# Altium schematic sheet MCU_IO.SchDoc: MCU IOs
size A3; Date: Not used; ApprovedBy: Not used; CheckedBy: Not used; Author: Not used; CompanyName: STMicroelectronics; DrawnBy: Not used; Engineer: Not used; Organization: Not used; Address1: Not used; Address2: Not used; Address3: Not used; Address4: Not used; DocumentNumber: Not used; Revision: Not used; SheetNumber: 3; SheetTotal: 16
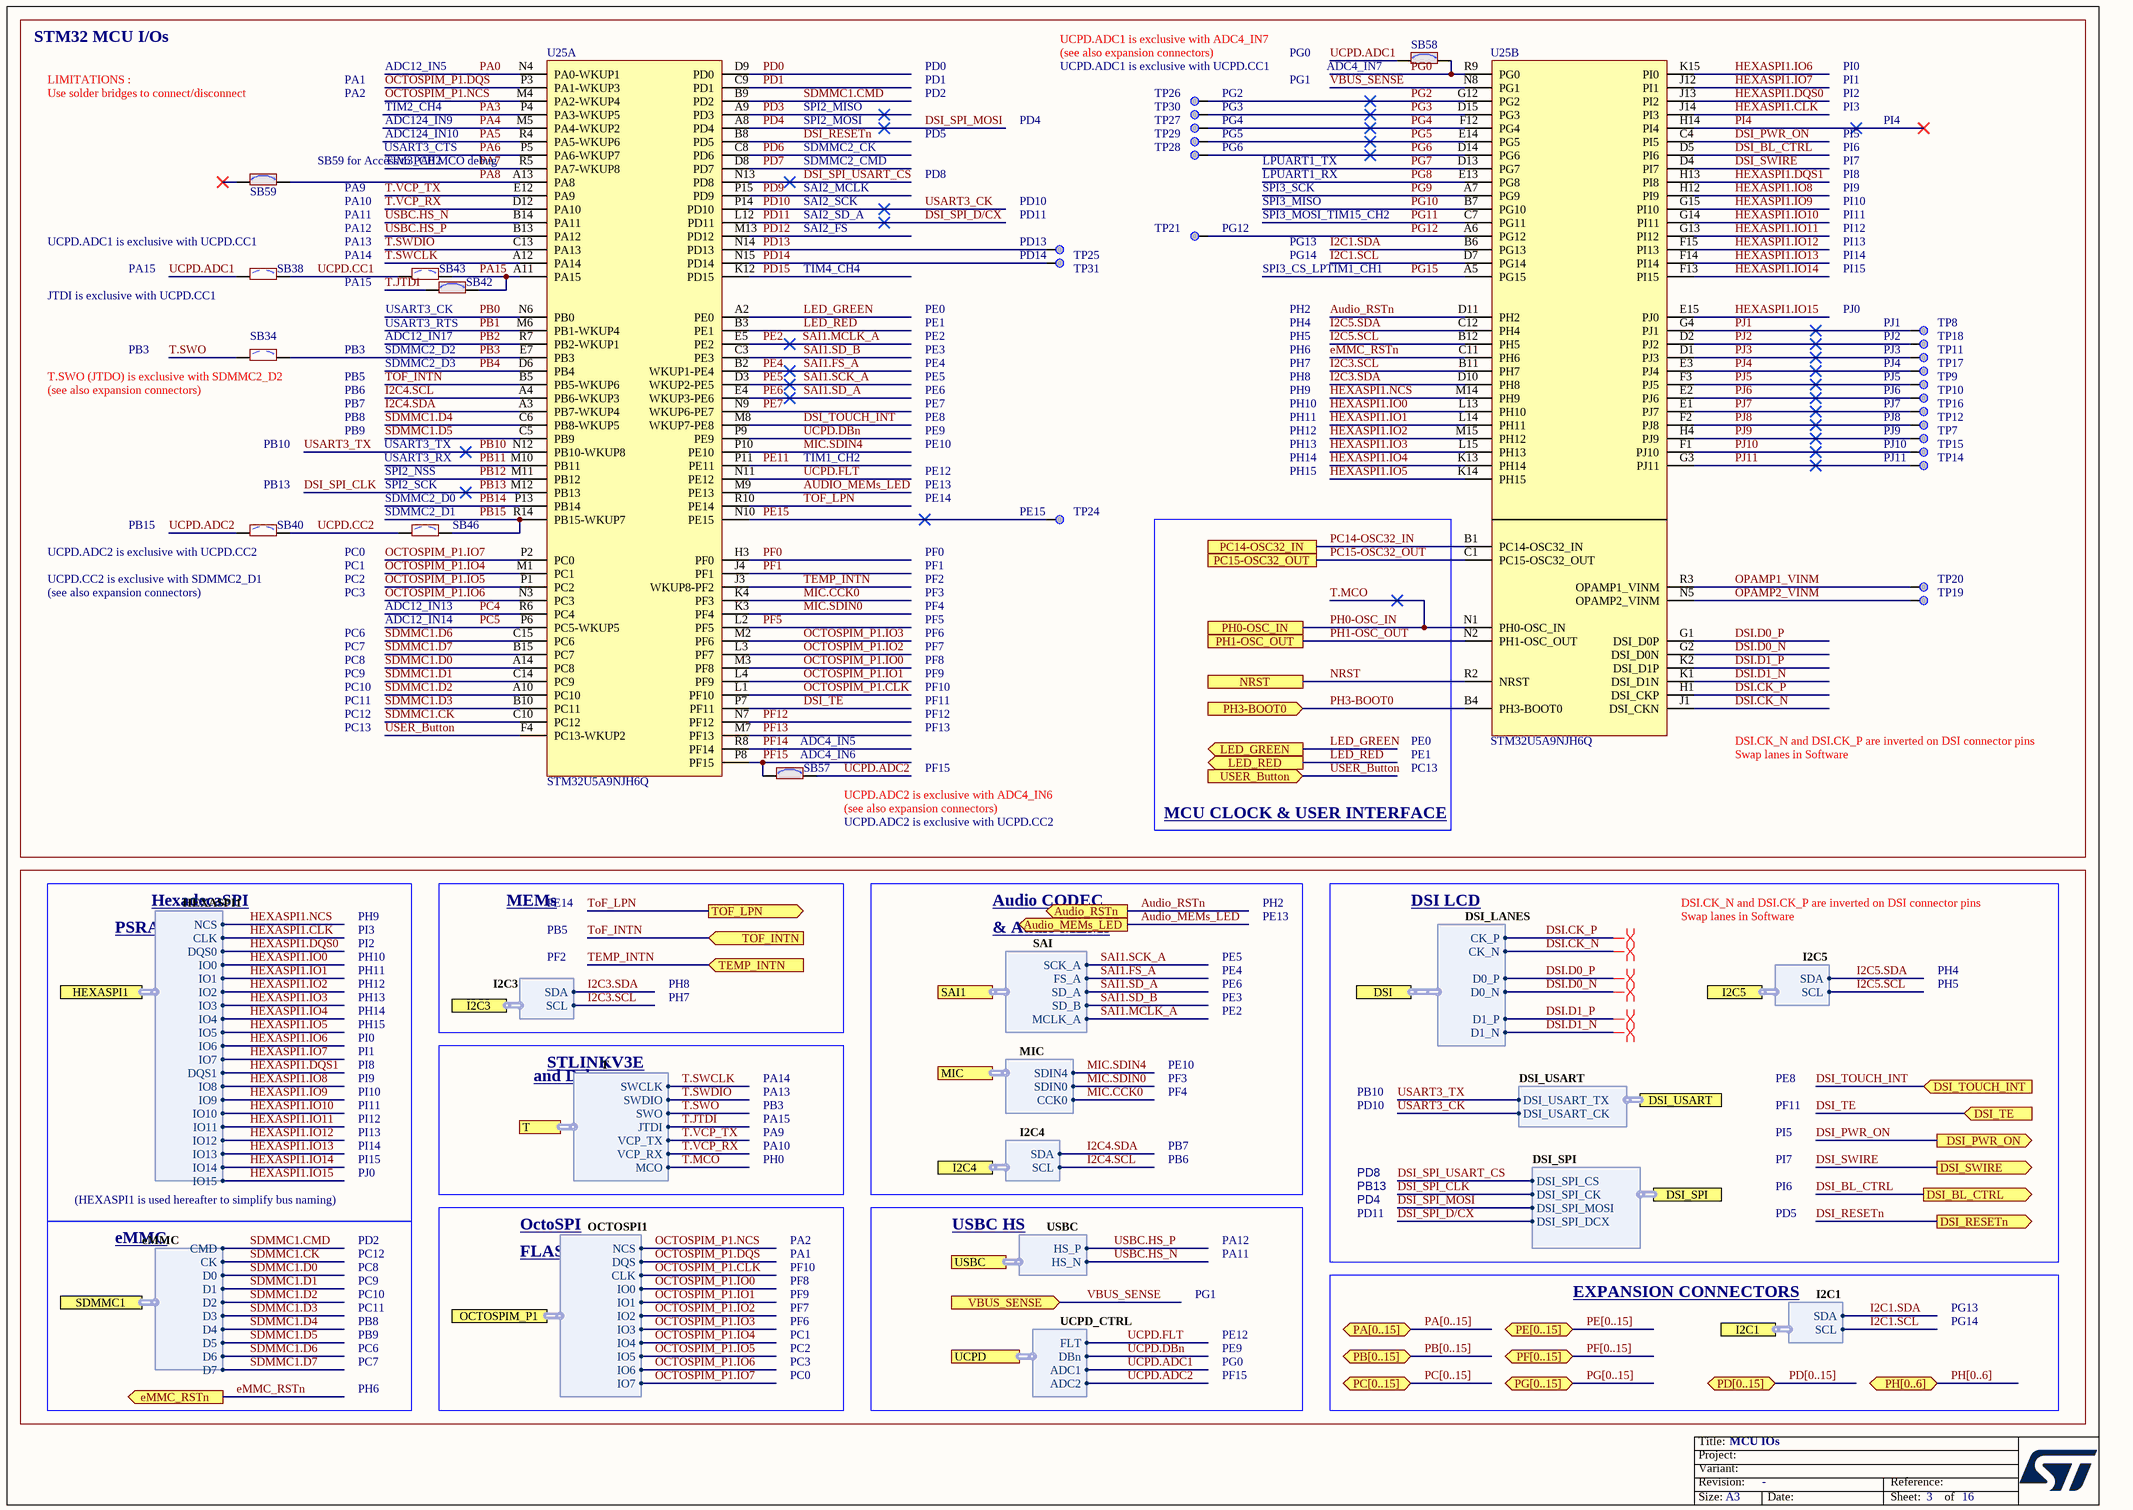
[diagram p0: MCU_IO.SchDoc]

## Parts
SB34  SB_OFF  [SOLDER-BRIDGE_R0402-0R]  (value not drawn)
SB38  SB_OFF  [SOLDER-BRIDGE_R0402-0R]  (value not drawn)
SB40  SB_OFF  [SOLDER-BRIDGE_R0402-0R]  (value not drawn)
SB42  SB_ON  [SOLDER-BRIDGE_R0402-0R]  (value not drawn)
SB43  SB_OFF  [SOLDER-BRIDGE_R0402-0R]  (value not drawn)
SB46  SB_OFF  [SOLDER-BRIDGE_R0402-0R]  (value not drawn)
SB57  SB_ON  [SOLDER-BRIDGE_R0402-0R]  (value not drawn)
SB58  SB_ON  [SOLDER-BRIDGE_R0402-0R]  (value not drawn)
SB59  SB_ON  [SOLDER-BRIDGE_R0402-0R]  (value not drawn)
TP7  Test Point  [TP_SMD_1MM]  (value not drawn)  (no BOM)
TP8  Test Point  [TP_SMD_1MM]  (value not drawn)  (no BOM)
TP9  Test Point  [TP_SMD_1MM]  (value not drawn)  (no BOM)
TP10  Test Point  [TP_SMD_1MM]  (value not drawn)  (no BOM)
TP11  Test Point  [TP_SMD_1MM]  (value not drawn)  (no BOM)
TP12  Test Point  [TP_SMD_1MM]  (value not drawn)  (no BOM)
TP14  Test Point  [TP_SMD_1MM]  (value not drawn)  (no BOM)
TP15  Test Point  [TP_SMD_1MM]  (value not drawn)  (no BOM)
TP16  Test Point  [TP_SMD_1MM]  (value not drawn)  (no BOM)
TP17  Test Point  [TP_SMD_1MM]  (value not drawn)  (no BOM)
TP18  Test Point  [TP_SMD_1MM]  (value not drawn)  (no BOM)
TP19  Test Point  [TP_SMD_1MM]  (value not drawn)  (no BOM)
TP20  Test Point  [TP_SMD_1MM]  (value not drawn)  (no BOM)
TP21  Test Point  [TP_SMD_1MM]  (value not drawn)  (no BOM)
TP24  Test Point  [TP_SMD_1MM]  (value not drawn)  (no BOM)
TP25  Test Point  [TP_SMD_1MM]  (value not drawn)  (no BOM)
TP26  Test Point  [TP_SMD_1MM]  (value not drawn)  (no BOM)
TP27  Test Point  [TP_SMD_1MM]  (value not drawn)  (no BOM)
TP28  Test Point  [TP_SMD_1MM]  (value not drawn)  (no BOM)
TP29  Test Point  [TP_SMD_1MM]  (value not drawn)  (no BOM)
TP30  Test Point  [TP_SMD_1MM]  (value not drawn)  (no BOM)
TP31  Test Point  [TP_SMD_1MM]  (value not drawn)  (no BOM)
U25  value STM32U5A9NJH6Q  [ICC_TFBGA216_13X13_P080_H1P10_CODE-A0L2]  (hidden comment: STM32U599NJH6Q_BGA216_SMPS)  (parts A,B of 3)

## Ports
Audio_MEMs_LED (out), Audio_RSTn (out), DSI (harness DSI_LANES), DSI_BL_CTRL (out), DSI_PWR_ON (out), DSI_RESETn (out), DSI_SPI (harness DSI_SPI), DSI_SWIRE (out), DSI_TE (in), DSI_TOUCH_INT (in), DSI_USART (harness DSI_USART), eMMC_RSTn (out), HEXASPI1 (harness HEXASPI1), I2C1 (harness I2C1), I2C3 (harness I2C3), I2C4 (harness I2C4), I2C5 (harness I2C5), LED_GREEN (out), LED_RED (out), MIC (harness MIC), NRST, OCTOSPIM_P1 (harness OCTOSPI1), PA[0..15] (bidir), PB[0..15] (bidir), PC14-OSC32_IN, PC15-OSC32_OUT, PC[0..15] (bidir), PD[0..15] (bidir), PE[0..15] (bidir), PF[0..15] (bidir), PG[0..15] (bidir), PH0-OSC_IN, PH1-OSC_OUT, PH3-BOOT0 (in), PH[0..6] (bidir), SAI1 (harness SAI), SDMMC1 (harness eMMC), T (harness T), TEMP_INTN (in), TOF_INTN (in), TOF_LPN (out), UCPD (harness UCPD_CTRL), USBC (harness USBC), USER_Button (in), VBUS_SENSE (in)

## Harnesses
T: SWCLK, SWDIO, SWO, JTDI, VCP_RX, VCP_TX, MCO
MIC: SDIN0, CCK0, SDIN4
OCTOSPI1: IO1, IO0, CLK, NCS, IO2, IO3, IO5, IO4, IO6, IO7, DQS
eMMC: D0, CMD, CK, D1, D2, D3, D4, D5, D6, D7
SAI: SD_B, FS_A, SD_A, SCK_A, MCLK_A
DSI_LANES: CK_P, CK_N, D0_P, D0_N, D1_N, D1_P
USBC: HS_P, HS_N
DSI_SPI: DSI_SPI_CS, DSI_SPI_MOSI, DSI_SPI_CK, DSI_SPI_DCX
DSI_USART: DSI_USART_CK, DSI_USART_TX
I2C4: SDA, SCL
I2C5: SDA, SCL
HEXASPI1: IO1, IO0, DQS0, NCS, IO2, IO3, IO5, IO4, IO6, IO7, CLK, DQS1, IO8, IO9, IO10, IO11, IO12, IO13, IO14, IO15
UCPD_CTRL: FLT, DBn, ADC1, ADC2
I2C1: SDA, SCL
I2C3: SDA, SCL

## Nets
AUDIO_MEMs_LED: U25.M9(PE13) ; port Audio_MEMs_LED
Audio_RSTn: U25.D11(PH2) ; port Audio_RSTn
DSI.CK_N: U25.J1(DSI_CKN) ; port DSI.CK_N
DSI.CK_P: U25.H1(DSI_CKP) ; port DSI.CK_P
DSI.D0_N: U25.G2(DSI_D0N) ; port DSI.D0_N
DSI.D0_P: U25.G1(DSI_D0P) ; port DSI.D0_P
DSI.D1_N: U25.K1(DSI_D1N) ; port DSI.D1_N
DSI.D1_P: U25.K2(DSI_D1P) ; port DSI.D1_P
DSI_BL_CTRL: U25.D5(PI6) ; port DSI_BL_CTRL
DSI_PWR_ON: U25.C4(PI5) ; port DSI_PWR_ON
DSI_RESETn: U25.B8(PD5) ; port DSI_RESETn
DSI_SPI_CLK: U25.M12(PB13) ; port DSI_SPI.DSI_SPI_CK  [also labelled PB13]
DSI_SPI_D/CX: U25.L12(PD11) ; port DSI_SPI.DSI_SPI_DCX  [also labelled PD11]
DSI_SPI_MOSI: U25.A8(PD4) ; port DSI_SPI.DSI_SPI_MOSI  [also labelled PD4]
DSI_SPI_USART_CS: U25.N13(PD8) ; port DSI_SPI.DSI_SPI_CS
DSI_SWIRE: U25.D4(PI7) ; port DSI_SWIRE
DSI_TE: U25.P7(PF11) ; port DSI_TE
DSI_TOUCH_INT: U25.M8(WKUP7-PE8) ; port DSI_TOUCH_INT
eMMC_RSTn: U25.C11(PH6) ; port eMMC_RSTn
HEXASPI1.CLK: U25.J14(PI3) ; port HEXASPI1.CLK
HEXASPI1.DQS0: U25.J13(PI2) ; port HEXASPI1.DQS0
HEXASPI1.DQS1: U25.H13(PI8) ; port HEXASPI1.DQS1
HEXASPI1.IO0: U25.L13(PH10) ; port HEXASPI1.IO0
HEXASPI1.IO1: U25.L14(PH11) ; port HEXASPI1.IO1
HEXASPI1.IO2: U25.M15(PH12) ; port HEXASPI1.IO2
HEXASPI1.IO3: U25.L15(PH13) ; port HEXASPI1.IO3
HEXASPI1.IO4: U25.K13(PH14) ; port HEXASPI1.IO4
HEXASPI1.IO5: U25.K14(PH15) ; port HEXASPI1.IO5
HEXASPI1.IO6: U25.K15(PI0) ; port HEXASPI1.IO6
HEXASPI1.IO7: U25.J12(PI1) ; port HEXASPI1.IO7
HEXASPI1.IO8: U25.H12(PI9) ; port HEXASPI1.IO8
HEXASPI1.IO9: U25.G15(PI10) ; port HEXASPI1.IO9
HEXASPI1.IO10: U25.G14(PI11) ; port HEXASPI1.IO10
HEXASPI1.IO11: U25.G13(PI12) ; port HEXASPI1.IO11
HEXASPI1.IO12: U25.F15(PI13) ; port HEXASPI1.IO12
HEXASPI1.IO13: U25.F14(PI14) ; port HEXASPI1.IO13
HEXASPI1.IO14: U25.F13(PI15) ; port HEXASPI1.IO14
HEXASPI1.IO15: U25.E15(PJ0) ; port HEXASPI1.IO15
HEXASPI1.NCS: U25.M14(PH9) ; port HEXASPI1.NCS
I2C1.SCL: U25.D7(PG14) ; port I2C1.SCL
I2C1.SDA: U25.B6(PG13) ; port I2C1.SDA
I2C3.SCL: U25.B11(PH7) ; port I2C3.SCL
I2C3.SDA: U25.D10(PH8) ; port I2C3.SDA
I2C4.SCL: U25.A4(PB6-WKUP3) ; port I2C4.SCL
I2C4.SDA: U25.A3(PB7-WKUP4) ; port I2C4.SDA
I2C5.SCL: U25.B12(PH5) ; port I2C5.SCL
I2C5.SDA: U25.C12(PH4) ; port I2C5.SDA
LED_GREEN: U25.A2(PE0) ; port LED_GREEN
LED_RED: U25.B3(PE1) ; port LED_RED
MIC.CCK0: U25.K4(PF3) ; port MIC.CCK0
MIC.SDIN0: U25.K3(PF4) ; port MIC.SDIN0
MIC.SDIN4: U25.P10(PE10) ; port MIC.SDIN4
NRST: U25.R2(NRST) ; port NRST
OCTOSPIM_P1.CLK: U25.L1(PF10) ; port OCTOSPIM_P1.CLK
OCTOSPIM_P1.DQS: U25.P3(PA1-WKUP3) ; port OCTOSPIM_P1.DQS
OCTOSPIM_P1.IO0: U25.M3(PF8) ; port OCTOSPIM_P1.IO0
OCTOSPIM_P1.IO1: U25.L4(PF9) ; port OCTOSPIM_P1.IO1
OCTOSPIM_P1.IO2: U25.L3(PF7) ; port OCTOSPIM_P1.IO2
OCTOSPIM_P1.IO3: U25.M2(PF6) ; port OCTOSPIM_P1.IO3
OCTOSPIM_P1.IO4: U25.M1(PC1) ; port OCTOSPIM_P1.IO4
OCTOSPIM_P1.IO5: U25.P1(PC2) ; port OCTOSPIM_P1.IO5
OCTOSPIM_P1.IO6: U25.N3(PC3) ; port OCTOSPIM_P1.IO6
OCTOSPIM_P1.IO7: U25.P2(PC0) ; port OCTOSPIM_P1.IO7
OCTOSPIM_P1.NCS: U25.M4(PA2-WKUP4) ; port OCTOSPIM_P1.NCS
OPAMP1_VINM: TP20.1 U25.R3(OPAMP1_VINM)
OPAMP2_VINM: TP19.1 U25.N5(OPAMP2_VINM)
PA0: U25.N4(PA0-WKUP1)
PA3: U25.P4(PA3-WKUP5)
PA4: U25.M5(PA4-WKUP2)
PA5: U25.R4(PA5-WKUP6)
PA6: U25.P5(PA6-WKUP7)
PA7: U25.R5(PA7-WKUP8)
PA8: SB59.2 U25.A13(PA8)
PA15: SB42.2 SB43.2 U25.A11(PA15)
PB0: U25.N6(PB0)
PB1: U25.M6(PB1-WKUP4)
PB2: U25.R7(PB2-WKUP1)
PB3: SB34.2 U25.E7(PB3)
PB4: U25.D6(PB4)
PB10: U25.N12(PB10-WKUP8) ; port DSI_USART.DSI_USART_TX  [also labelled USART3_TX]
PB11: U25.M10(PB11)
PB12: U25.M11(PB12)
PB14: U25.P13(PB14)
PB15: SB46.2 U25.R14(PB15-WKUP7)
PC4: U25.R6(PC4)
PC5: U25.P6(PC5-WKUP5)
PC14-OSC32_IN: U25.B1(PC14-OSC32_IN) ; port PC14-OSC32_IN
PC15-OSC32_OUT: U25.C1(PC15-OSC32_OUT) ; port PC15-OSC32_OUT
PD0: U25.D9(PD0)
PD1: U25.C9(PD1)
PD3: U25.A9(PD3)
PD6: U25.C8(PD6)
PD7: U25.D8(PD7)
PD9: U25.P15(PD9)
PD10: U25.P14(PD10) ; port DSI_USART.DSI_USART_CK  [also labelled USART3_CK]
PD12: U25.M13(PD12)
PD13: TP25.1 U25.N14(PD13)
PD14: TP31.1 U25.N15(PD14)
PD15: U25.K12(PD15)
PE2: U25.E5(PE2) ; port SAI1.MCLK_A  [also labelled SAI1.MCLK_A]
PE4: U25.B2(WKUP1-PE4) ; port SAI1.FS_A  [also labelled SAI1.FS_A]
PE5: U25.D3(WKUP2-PE5) ; port SAI1.SCK_A  [also labelled SAI1.SCK_A]
PE6: U25.E4(WKUP3-PE6) ; port SAI1.SD_A  [also labelled SAI1.SD_A]
PE7: U25.N9(WKUP6-PE7)
PE11: U25.P11(PE11)
PE15: TP24.1 U25.N10(PE15)
PF0: U25.H3(PF0)
PF1: U25.J4(PF1)
PF5: U25.L2(PF5)
PF12: U25.N7(PF12)
PF13: U25.M7(PF13)
PF14: U25.R8(PF14)
PF15: SB57.1 U25.P8(PF15)
PG0: SB58.2 U25.R9(PG0)
PG2: TP26.1 U25.G12(PG2)
PG3: TP30.1 U25.D15(PG3)
PG4: TP27.1 U25.F12(PG4)
PG5: TP29.1 U25.E14(PG5)
PG6: TP28.1 U25.D14(PG6)
PG7: U25.D13(PG7)
PG8: U25.E13(PG8)
PG9: U25.A7(PG9)
PG10: U25.B7(PG10)
PG11: U25.C7(PG11)
PG12: TP21.1 U25.A6(PG12)
PG15: U25.A5(PG15)
PH0-OSC_IN: U25.N1(PH0-OSC_IN) ; port PH0-OSC_IN, port T.MCO  [also labelled T.MCO]
PH1-OSC_OUT: U25.N2(PH1-OSC_OUT) ; port PH1-OSC_OUT
PH3-BOOT0: U25.B4(PH3-BOOT0) ; port PH3-BOOT0
PI4: U25.H14(PI4)
PJ1: TP8.1 U25.G4(PJ1)
PJ2: TP18.1 U25.D2(PJ2)
PJ3: TP11.1 U25.D1(PJ3)
PJ4: TP17.1 U25.E3(PJ4)
PJ5: TP9.1 U25.F3(PJ5)
PJ6: TP10.1 U25.E2(PJ6)
PJ7: TP16.1 U25.E1(PJ7)
PJ8: TP12.1 U25.F2(PJ8)
PJ9: TP7.1 U25.H4(PJ9)
PJ10: TP15.1 U25.F1(PJ10)
PJ11: TP14.1 U25.G3(PJ11)
SAI1.SD_B: U25.C3(PE3) ; port SAI1.SD_B
SDMMC1.CK: U25.C10(PC12) ; port SDMMC1.CK
SDMMC1.CMD: U25.B9(PD2) ; port SDMMC1.CMD
SDMMC1.D0: U25.A14(PC8) ; port SDMMC1.D0
SDMMC1.D1: U25.C14(PC9) ; port SDMMC1.D1
SDMMC1.D2: U25.A10(PC10) ; port SDMMC1.D2
SDMMC1.D3: U25.B10(PC11) ; port SDMMC1.D3
SDMMC1.D4: U25.C6(PB8-WKUP5) ; port SDMMC1.D4
SDMMC1.D5: U25.C5(PB9) ; port SDMMC1.D5
SDMMC1.D6: U25.C15(PC6) ; port SDMMC1.D6
SDMMC1.D7: U25.B15(PC7) ; port SDMMC1.D7
T.JTDI: SB42.1 ; port T.JTDI
T.SWCLK: U25.A12(PA14) ; port T.SWCLK
T.SWDIO: U25.C13(PA13) ; port T.SWDIO
T.SWO: SB34.1 ; port T.SWO
T.VCP_RX: U25.D12(PA10) ; port T.VCP_RX
T.VCP_TX: U25.E12(PA9) ; port T.VCP_TX
TEMP_INTN: U25.J3(WKUP8-PF2) ; port TEMP_INTN
ToF_INTN: U25.B5(PB5-WKUP6) ; port TOF_INTN
ToF_LPN: U25.R10(PE14) ; port TOF_LPN
UCPD.ADC1: SB38.1 SB58.1 ; port UCPD.ADC1
UCPD.ADC2: SB40.1 SB57.2 ; port UCPD.ADC2
UCPD.CC1: SB38.2 SB43.1
UCPD.CC2: SB40.2 SB46.1
UCPD.DBn: U25.P9(PE9) ; port UCPD.DBn
UCPD.FLT: U25.N11(PE12) ; port UCPD.FLT
USBC.HS_N: U25.B14(PA11) ; port USBC.HS_N
USBC.HS_P: U25.B13(PA12) ; port USBC.HS_P
USER_Button: U25.F4(PC13-WKUP2) ; port USER_Button
VBUS_SENSE: U25.N8(PG1) ; port VBUS_SENSE

Not connected (* = marked no-connect by the designer): SB59 1*

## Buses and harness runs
bus PA[0..15] = port PA[0..15]
bus PB[0..15] = port PB[0..15]
bus PC[0..15] = port PC[0..15]
bus PD[0..15] = port PD[0..15]
bus PE[0..15] = port PE[0..15]
bus PF[0..15] = port PF[0..15]
bus PG[0..15] = port PG[0..15]
bus PH[0..6] = port PH[0..6]

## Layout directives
differential pair; rule Impedance Constraint [Min = 95.00    Max = 105.0    ]: DSI.CK_N, DSI.CK_P, DSI.D0_N, DSI.D0_P, DSI.D1_N, DSI.D1_P

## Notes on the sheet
- STM32 MCU I/Os
- UCPD.ADC1 is exclusive with ADC4_IN7
- Use solder bridges to connect/disconnect
- LIMITATIONS :
- PA1
- PA2
- TIM2_CH4
- ADC12_IN5
- SPI2_MISO
- PD2
- PD1
- PD0
- UCPD.ADC1 is exclusive with UCPD.CC1
- (see also expansion connectors)
- PG2
- PG3
- PG1
- PG0
- (near SB58) ADC4_IN7
- PI0
- PI1
- PI2
- PI3
- (near SB59) SB59 for Access to PA8 MCO debug
- ADC124_IN9
- ADC124_IN10
- TIM3_CH2
- USART3_CTS
- SDMMC2_CK
- SDMMC2_CMD
- SPI2_MOSI
- PD8
- PD5
- PD4
- PG4
- PG5
- PG6
- LPUART1_TX
- LPUART1_RX
- PI8
- PI6
- PI7
- PI5
- PI4
- (near SB38) UCPD.ADC1 is exclusive with UCPD.CC1
- PA13
- PA10
- PA9
- PA12
- PA11
- SAI2_MCLK
- SAI2_SCK
- SAI2_SD_A
- SAI2_FS
- PD10
- PD11
- PD13
- (near TP21) PG12
- SPI3_SCK
- SPI3_MISO
- SPI3_MOSI_TIM15_CH2
- PG13
- PI9
- PI10
- PI11
- PI12
- PI13
- (near SB38) JTDI is exclusive with UCPD.CC1
- PA15
- PA14
- (near SB42) USART3_CK
- TIM4_CH4
- PE0
- PD14
- SPI3_CS_LPTIM1_CH1
- PG14
- PH2
- PI14
- PI15
- PJ0
- (near SB34) T.SWO (JTDO) is exclusive with SDMMC2_D2
- PB3
- PB5
- SDMMC2_D2
- SDMMC2_D3
- ADC12_IN17
- USART3_RTS
- PE1
- PE2
- PE3
- PE4
- PE5
- PH4
- PH5
- PH6
- PH7
- PH8
- PJ1
- PJ2
- PJ3
- PJ4
- PJ5
- (near SB34) (see also expansion connectors)
- PB10
- PB8
- PB9
- PB6
- PB7
- USART3_TX
- PE6
- PE7
- PE8
- PE10
- PE9
- PH9
- PH11
- PH12
- PH13
- PH10
- PJ6
- PJ7
- PJ8
- PJ9
- PJ10
- (near SB40) PB13
- (near SB46) SDMMC2_D0
- (near SB46) SDMMC2_D1
- (near SB46) SPI2_SCK
- SPI2_NSS
- USART3_RX
- TIM1_CH2
- PE13
- PE14
- PE12
- (near TP24) PE15
- PH14
- PH15
- PJ11
- (near SB40) UCPD.CC2 is exclusive with SDMMC2_D1
- (near SB40) UCPD.ADC2 is exclusive with UCPD.CC2
- PB15
- PC0
- PC1
- PC2
- PF1
- PF0
- PF2
- PC6
- PC7
- PC3
- ADC12_IN14
- ADC12_IN13
- PF6
- PF7
- PF4
- PF3
- PF5
- PC9
- PC12
- PC8
- PC10
- PC11
- PF9
- PF8
- PF10
- PF12
- PF11
- PC13
- (near SB57) ADC4_IN5
- (near SB57) ADC4_IN6
- PF13
- PF15
- DSI.CK_N and DSI.CK_P are inverted on DSI connector pins
- Swap lanes in Software
- (near SB57) UCPD.ADC2 is exclusive with ADC4_IN6
- UCPD.ADC2 is exclusive with UCPD.CC2
- (near SB57) (see also expansion connectors)
- MCU CLOCK & USER INTERFACE
- HexadecaSPI
- MEMs
- Audio CODEC
- DSI LCD
- PSRAM
- & Audio MEMs
- and Debug
- STLINKV3E
- PH0
- PB13
- (HEXASPI1 is used hereafter to simplify bus naming)
- eMMC
- OctoSPI
- FLASH
- USBC HS
- EXPANSION CONNECTORS

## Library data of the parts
SB34 SB38 SB40 SB43 SB46 = MCD-02162: Solder Bridge 0402 OFF; Part_Type: Misc; Manufacturer_Part_Number: RC0402JR-070RL; Manufacturer: YAGEO; Part_Preference: Recommended; Order_Code_RS: 618-5804; Component_Country_Of_Origin: China
SB42 SB57-SB59 = MCD-01618: Solder Bridge 0402 ON; Part_Type: Misc; Manufacturer_Part_Number: RC0402JR-070RL; Manufacturer: YAGEO; Part_Preference: Recommended; Order_Code_RS: 618-5804; Component_Country_Of_Origin: China
TP7-TP12 TP14-TP21 TP24-TP31 = MCD-00074: Test Point 1mm; Part_Type: Misc; Part_Preference: Recommended
U25 = MCD-03270: MCU, ARM Cortex-M33, 4MB Flash, 2.5MB RAM, With Crypto; Part_Type: IC; Part_Preference: Recommended; Manufacturer: STMICROELECTRONICS; Component_Country_Of_Origin: Unknown; ShowFields: YES; ID: 5386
